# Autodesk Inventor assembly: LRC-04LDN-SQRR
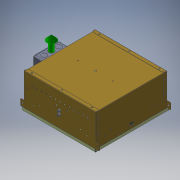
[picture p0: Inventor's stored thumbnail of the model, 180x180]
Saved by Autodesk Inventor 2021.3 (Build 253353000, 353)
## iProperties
Part Number: LRC-04LDN-SQRR
Document SubType Name: Assembly
Designer: JChurch
load_classification: Lighting
motor: 0 ul
Author: JChurch
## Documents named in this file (6)
- X:\Revit Files\0000-Un-Zipped\COB\LRC-04LDN-SQR\LRC-04LDN-SQRR.iam
- X:\INVENTOR\830\830557-00-00.iam
- X:\INVENTOR\881\881088-00-00.iam
- X:\INVENTOR\750\750206-00-00.iam
- X:\INVENTOR\725\725292-00-00.ipt
- X:\Revit Files\0000-Un-Zipped\COB\LRC-04LDN-SQR\LRC-04LDN-SQRR_Substitute_1.ipt
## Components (5 placed, 5 different names)
1. 830557-00-00:1 [sub-assembly] — Mate:1, Mate:2, Mate:3, Mate:4, Tangent:1, Angle:1, Mate:7
2. 881088-00-00:1 [sub-assembly] — Mate:4, Tangent:1, Angle:1
3. 750206-00-00:1 [sub-assembly] — Mate:5, Mate:6, Flush:1, Mate:7, Mate:8, Mate:9
4. 725292-00-00:1 — Mate:5, Mate:6, Flush:1
5. LRC-04LDN-SQRR_Substitute_1:1
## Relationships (12: Mate 9, Tangent 1, Angle 1, Flush 1)
- Mate:1: 830557-00-00:1
- Mate:2: 830557-00-00:1
- Mate:3: 830557-00-00:1
- Mate:4: 830557-00-00:1 ↔ 881088-00-00:1
- Tangent:1: 830557-00-00:1 ↔ 881088-00-00:1
- Angle:1: 830557-00-00:1 ↔ 881088-00-00:1
- Mate:5: 750206-00-00:1 ↔ 725292-00-00:1
- Mate:6: 750206-00-00:1 ↔ 725292-00-00:1
- Flush:1: 750206-00-00:1 ↔ 725292-00-00:1
- Mate:7: 830557-00-00:1 ↔ 750206-00-00:1
- Mate:8: 750206-00-00:1
- Mate:9: 750206-00-00:1
